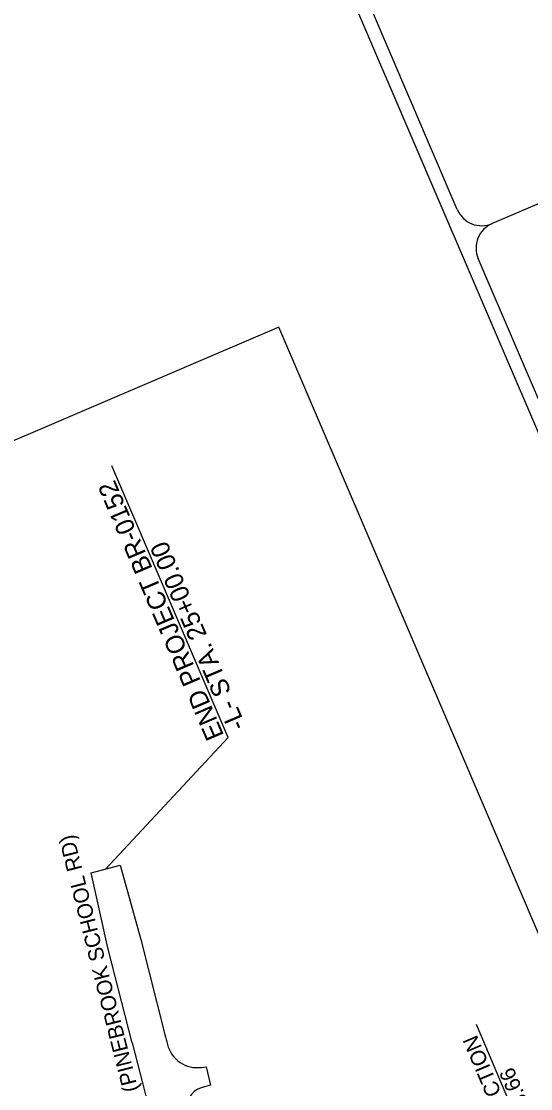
# Model space of a CAD drawing. Extents: x 1550250 to 1553210, y 808906 to 812497.
# Drawn here: x 1551614 to 1551945, y 811095 to 811788 of the extents above; entities that cross this region are included whole.
import ezdxf

# ---------------------------------------------------------------- set-up
doc = ezdxf.new("R2010")
doc.units = 0
for name, color, linetype in [('P_RDY_DSN_Text', 7, 'Continuous'), ('P_RDY_Shade_Light', 7, 'Continuous'), ('Sheet_Plan_CELL', 7, 'Continuous'), ('Sheet_Title_CELL', 7, 'Continuous')]:
    doc.layers.add(name, color=color, linetype=linetype)

msp = doc.modelspace()

# ---------------------------------------------------------------- linework, layer by layer
at = {"layer": 'P_RDY_DSN_Text'}
for points in [[(1551668.9, 811237.55), (1551748.45, 811322.94), (1551672.96, 811499.3)], [(1552046.49, 810930.61), (1551967.31, 811000.28), (1551909.64, 811136.59)]]:
    msp.add_lwpolyline(points, dxfattribs=at)
at = {"layer": 'P_RDY_Shade_Light'}
for points in [[(1551686.15, 811124.84), (1551670.53, 811186.38), (1551659.61, 811235.19), (1551678.44, 811239.97), (1551691.86, 811191.79), (1551707.48, 811130.26)], [(1551731.23, 811108.84), (1551734.15, 811109.24), (1551737.03, 811097.33), (1551731.75, 811095.81)]]:
    msp.add_lwpolyline(points, dxfattribs=at)
for centre, radius, start, end in [((1554524.17, 811845.14), 2906, 194.24112, 194.37475), ((1554524.17, 811845.14), 2928, 194.24112, 196.42272), ((1551728.52, 811128.66), 20, 194.37475, 277.78131), ((1551735.88, 811081.39), 15, 105.99998, 195.31833)]:
    msp.add_arc(centre, radius, start, end, dxfattribs=at)
at = {"layer": 'Sheet_Plan_CELL'}
msp.add_lwpolyline([(1551190.18, 811336.14), (1551800.19, 809911.05), (1552391.43, 810164.14), (1551781.41, 811589.22)], close=True, dxfattribs=at)
at = {"layer": 'Sheet_Title_CELL'}
for p, q in [((1552747.76, 809656.43), (1551686.13, 812136.57)), ((1551897.14, 811665.52), (1551694.05, 812139.97)), ((1552173.52, 811765.06), (1551919.79, 811656.45)), ((1552046.33, 811317), (1551910.72, 811633.8))]:
    msp.add_line(p, q, dxfattribs=at)
for centre, start, end in [((1551913, 811672.31), 203.1736, 293.1736), ((1551926.58, 811640.59), 113.1736, 203.1736)]:
    msp.add_arc(centre, 17.25, start, end, dxfattribs=at)

# ---------------------------------------------------------------- texts
at = {"layer": 'P_RDY_DSN_Text'}
for s, height, rotation, p in [('END PROJECT BR-0152', 12, 113.1736, (1551745.99, 811324.29)), ('-L- STA. 25+00.00', 12, 113.1736, (1551760.24, 811330.39)), ('-L-  SR 1436 (PINEBROOK SCHOOL RD)', 10, 104.24112, (1551709.9, 811017.07)), ('END CONSTRUCTION', 10, 113.1736, (1551964.55, 811002.16)), ('-Y- STA. 19+93.66', 10, 113.1736, (1551976.96, 811007.48))]:
    msp.add_text(s, height=height, rotation=rotation, dxfattribs=at).set_placement(p)

doc.saveas('drawing.dxf')
